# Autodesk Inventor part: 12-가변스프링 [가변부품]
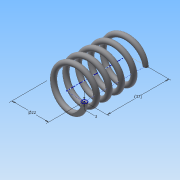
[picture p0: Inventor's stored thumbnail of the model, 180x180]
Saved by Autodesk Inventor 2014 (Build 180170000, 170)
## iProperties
Created: 2015-09
Part Number: 12-가변스프링 [가변부품]
Material: 강철, 탄소
Document SubType Name: Modeling
Designer: study
Density: 7.87 g/cm^3
Appearance: 반연마
Mass: 18.8111 g
Surface Area: 32.4633 cm^2
Volume: 2.39023 cm^3
Author: study
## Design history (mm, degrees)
sketch "스케치1"
  geometry: L1 (0, 0)-(11, 0); L2 (11, 0)-(11, 28.893); L3 (11, 28.893)-(0, 28.893); L4 (0, 28.893)-(0, 0); C1 r 1.5 at (11, 0)
  constraints: 8 end point, 2 parallel, 1 centre point, 1 coincident, 1 horizontal, 1 perpendicular
  dimensions: "d0" = 22 diameter of L2 L4; "d1" = 28.89259 distance of L1.end L2.end (derived); "d2" = 3 diameter of C1
feature "코일1" pitch "d3" = 10; turns "d5" = 5; dims "d4" = 28.89259 (= d1), "d6" = 0, angle "d7" = 90 deg, angle "d8" = 90 deg, "d9" = 0, "d10" = 0
node "작업 평면1"
sketch "스케치2"
  geometry: L1 (-12.5, 0)-(-9.5, 0) reference; 1 further point
  constraints: 1 horizontal alignment
extrude "돌출1" cut sketch "스케치2" stored distance "d12" = 10; taper "d13" = 0 deg
node "작업 평면2"
sketch "스케치3"
  geometry: L1 (-9.5, 0)-(-12.5, 0) reference; 1 further point
  constraints: 1 horizontal alignment
extrude "돌출2" cut sketch "스케치3" stored distance "d15" = 10; taper "d16" = 0 deg
node "솔리드1"
node "절단 모서리 투영1"
node "절단 모서리 투영2"
other parameters: "d11" = 0, "d14" = 28.89259 (= d1)
